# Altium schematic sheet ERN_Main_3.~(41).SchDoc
size A; SheetNumber: 3; SheetTotal: 4; SPICEModelCacheXVWYUVSQ: <root> / <DocumentId>XVWYUVSQ</DocumentId> / <CacheFrame Number="0"> / <Model Name="irf1010" Kind="CKT"> / <Text>*IRF1010 MCE 4-2-96 / *55V  75A .014 ohm HEXFET pkg:TO-220 2,1,3 / .SUBCKT IRF1010  10 20 40 40 / M1   1  2  3  3  DMOS L=1U W=1U / RD  10  1  5.65M / RS  30  3  1.35M / RG  20  2  12.1 / CGS  2  3  2.15N / EGD 12  0  2  1  1 / VFB 14  0  0 / FFB  2  1  VFB  1 / CGD 13 14  4.49N / R1  13  0  1 / D1  12 13  DLIM / DDG 15 14  DCGD / R2  12 15  1 / D2  15  0  DLIM / DSD  3 10  DSUB / LS  30 40  7.5N / .MODEL DMOS NMOS (LEVEL=3 THETA=60M VMAX=114K ETA=2M VTO=3 KP=19.4) / .MODEL DCGD D (CJO=4.49N VJ=.6 M=.68) / .MODEL DSUB D (IS=311N N=1.5 RS=8.67M BV=55 CJO=4.08N VJ=.8 M=.42 TT=100N) / .MODEL DLIM D (IS=100U) / .ENDS IRF1010</Text> / </Model> / </CacheFrame> / </root>
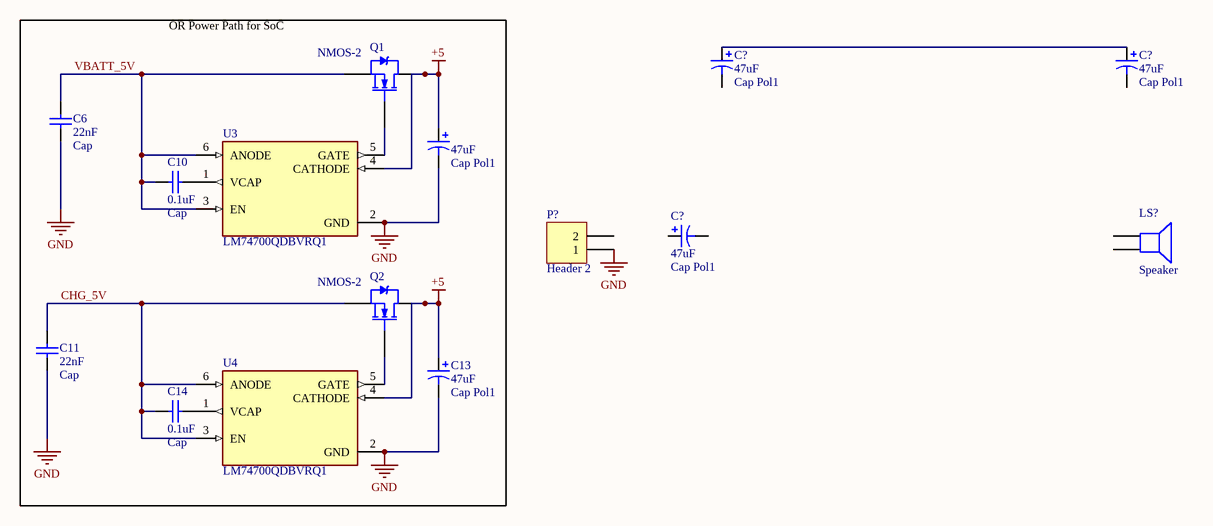
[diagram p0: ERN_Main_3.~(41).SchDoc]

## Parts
(Parts that share a designator on the sheet are numbered #1, #2 ... from top to bottom, then left to right.)
?  Cap Pol1  value 47uF  [RB7.6-15]
C6  Cap  value 22nF  [RAD-0.3]
C10  Cap  value 0.1uF  [RAD-0.3]
C11  Cap  value 22nF  [RAD-0.3]
C13  Cap Pol1  value 47uF  [RB7.6-15]
C14  Cap  value 0.1uF  [RAD-0.3]
C?#1  Cap Pol1  value 47uF  [RB7.6-15]
C?#2  Cap Pol1  value 47uF  [RB7.6-15]
C?#3  Cap Pol1  value 47uF  [RB7.6-15]
LS?  Speaker  [PIN2]
P?  Header 2  [HDR1X2]
Q1  NMOS-2  [TO-220AB]
Q2  NMOS-2  [TO-220AB]
U3  LM74700QDBVRQ1  [SOT95P280X145-6N]
U4  LM74700QDBVRQ1  [SOT95P280X145-6N]

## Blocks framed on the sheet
OR Power Path for SoC: ? C6 C10 C11 C13 C14 Q1 Q2 U3 U4

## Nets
+5: ?.1 C13.1 Q1.2(D) Q2.2(D) U3.4(CATHODE) U4.4(CATHODE)
GND: ?.2 C6.1 C11.1 C13.2 P?.1 U3.2(GND) U4.2(GND)
CHG_5V: C11.2 C14.2 Q2.3(S) U4.3(EN) U4.6(ANODE)
VBATT_5V: C6.2 C10.2 Q1.3(S) U3.3(EN) U3.6(ANODE)
NetC10_1: C10.1 U3.1(VCAP)
NetC14_1: C14.1 U4.1(VCAP)
NetC?#1_1: C?#1.1 C?#2.1
NetQ1_1: Q1.1(G) U3.5(GATE)
NetQ2_1: Q2.1(G) U4.5(GATE)

Not connected (* = marked no-connect by the designer): C?#1 2; C?#2 2; C?#3 1 2; LS? 1 2; P? 2

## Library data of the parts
? C13 C?#1-C?#3 = Cap Pol1: Polarized Capacitor (Radial)
C6 C10 C11 C14 = Cap: Capacitor
LS? = Speaker: Loudspeaker
P? = Header 2: Header, 2-Pin
Q1 Q2 = NMOS-2: N-Channel Power MOSFET; Note: Pin 2 is electrically connected to pin 4.
U3 U4 = LM74700QDBVRQ1: 3.2-V to 65-V, 80-uA IQ automotive ideal diode controller; MF: Texas Instruments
